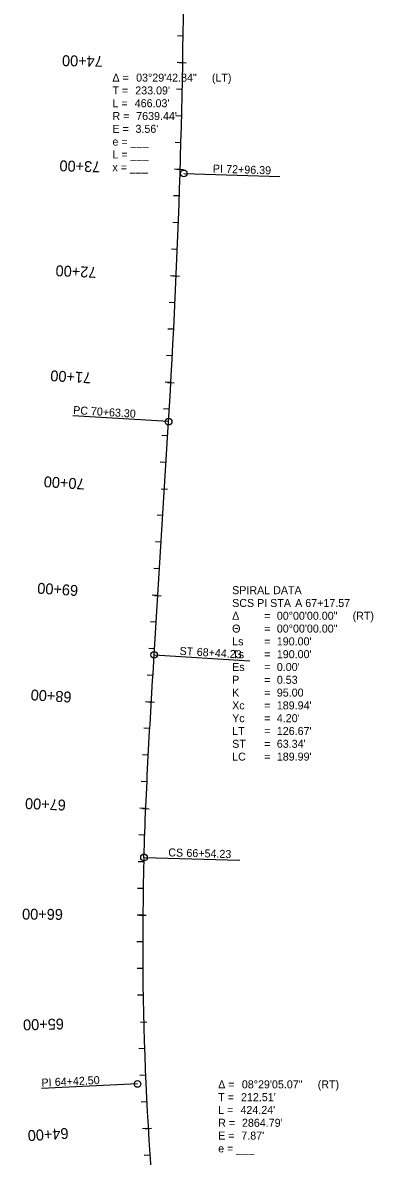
# Model space of a CAD drawing. Extents: x 11526485 to 11527255, y 9590594 to 9599170.
# Drawn here: x 11526485 to 11526814, y 9594882 to 9595945 of the extents above; entities that cross this region are included whole.
import ezdxf

# ---------------------------------------------------------------- set-up
doc = ezdxf.new("R2010")
doc.units = 0
for name, color, linetype in [('Alignment', 7, 'Continuous'), ('Default', 7, 'Continuous'), ('TextAlignment', 7, 'Continuous'), ('TextAlignmentLrg', 7, 'Continuous'), ('TextAlignmentSml', 7, 'Continuous')]:
    doc.layers.add(name, color=color, linetype=linetype)

msp = doc.modelspace()

# ---------------------------------------------------------------- linework, layer by layer
at = {"layer": 'Alignment'}
msp.add_line((11526608.5, 9595352.3), (11526622, 9595570.9), dxfattribs=at)
for centre, radius, start, end in [((11518997, 9596041.3), 7639.4, 356.46953, 359.96476), ((11529462.5, 9595081), 2864.8, 178.3695, 186.8543)]:
    msp.add_arc(centre, radius, start, end, dxfattribs=at)
msp.add_open_spline([(11526598.9, 9595162.5), (11526599.3, 9595178.3), (11526600.5, 9595210), (11526602.9, 9595257.4), (11526605.5, 9595304.8), (11526607.5, 9595336.4), (11526608.5, 9595352.3)], degree=3, dxfattribs=at)
at = {"layer": 'Default'}
msp.add_line((11526608.5, 9595352.3), (11526622, 9595570.9), dxfattribs=at)
for centre, radius, start, end in [((11518997, 9596041.3), 7639.4, 356.46953, 359.96476), ((11529462.5, 9595081), 2864.8, 178.3695, 186.8543)]:
    msp.add_arc(centre, radius, start, end, dxfattribs=at)
msp.add_open_spline([(11526598.9, 9595162.5), (11526599.3, 9595178.3), (11526600.5, 9595210), (11526602.9, 9595257.4), (11526605.5, 9595304.8), (11526607.5, 9595336.4), (11526608.5, 9595352.3)], degree=3, dxfattribs=at)
at = {"layer": 'TextAlignment'}
for p, q in [((11526636.3, 9595803.6), (11526726.3, 9595800.8)), ((11526726.3, 9595800.8), (11526726.3, 9595800.8)), ((11526622, 9595570.9), (11526532.2, 9595576.5)), ((11526532.2, 9595576.5), (11526532.2, 9595576.5)), ((11526608.5, 9595352.3), (11526698.3, 9595346.7)), ((11526698.3, 9595346.7), (11526698.3, 9595346.7)), ((11526598.9, 9595162.5), (11526688.9, 9595159.9)), ((11526598.9, 9595162.5), (11526688.9, 9595159.9)), ((11526688.9, 9595159.9), (11526688.9, 9595159.9)), ((11526688.9, 9595159.9), (11526688.9, 9595159.9)), ((11526592.8, 9594950.1), (11526502.9, 9594946)), ((11526502.9, 9594946), (11526502.9, 9594946))]:
    msp.add_line(p, q, dxfattribs=at)
for centre in [(11526636.3, 9595803.6), (11526622, 9595570.9), (11526608.5, 9595352.3), (11526598.9, 9595162.5), (11526598.9, 9595162.5), (11526592.8, 9594950.1)]:
    msp.add_circle(centre, 3.12, dxfattribs=at)
at = {"layer": 'TextAlignmentLrg'}
for p, q in [((11526635.3, 9595907.3), (11526629.9, 9595907.4)), ((11526632.9, 9595807.3), (11526627.4, 9595807.5)), ((11526629.2, 9595707.4), (11526623.7, 9595707.7)), ((11526624.2, 9595607.5), (11526618.7, 9595607.9)), ((11526615, 9595507.9), (11526621.1, 9595507.5)), ((11526611.9, 9595407.9), (11526606.5, 9595408.3)), ((11526605.8, 9595308.1), (11526600.4, 9595308.4)), ((11526600.5, 9595208.2), (11526595.1, 9595208.5)), ((11526597.9, 9595108.3), (11526592.4, 9595108.3)), ((11526595.6, 9595008.2), (11526601.7, 9595008.4)), ((11526602.9, 9594908.4), (11526597.5, 9594908.1))]:
    msp.add_line(p, q, dxfattribs=at)
at = {"layer": 'TextAlignmentSml'}
for p, q in [((11526635.7, 9595932.3), (11526630.2, 9595932.4)), ((11526632.3, 9595907.4), (11526638.4, 9595907.3)), ((11526634.8, 9595882.3), (11526629.4, 9595882.4)), ((11526634.3, 9595857.3), (11526628.8, 9595857.5)), ((11526633.6, 9595832.3), (11526628.2, 9595832.5)), ((11526629.8, 9595807.4), (11526636, 9595807.3)), ((11526632.1, 9595782.4), (11526626.6, 9595782.5)), ((11526631.2, 9595757.4), (11526625.8, 9595757.6)), ((11526630.2, 9595732.4), (11526624.8, 9595732.6)), ((11526626.1, 9595707.6), (11526632.2, 9595707.3)), ((11526628.1, 9595682.4), (11526622.6, 9595682.7)), ((11526626.8, 9595657.5), (11526621.4, 9595657.7)), ((11526625.5, 9595632.5), (11526620.1, 9595632.8)), ((11526621.1, 9595607.7), (11526627.2, 9595607.4)), ((11526622.7, 9595582.6), (11526617.3, 9595582.9)), ((11526621.2, 9595557.6), (11526615.7, 9595558)), ((11526619.6, 9595532.7), (11526614.2, 9595533)), ((11526615, 9595507.9), (11526621.1, 9595507.5)), ((11526616.6, 9595482.8), (11526611.1, 9595483.1)), ((11526615, 9595457.8), (11526609.6, 9595458.2)), ((11526613.5, 9595432.9), (11526608, 9595433.2)), ((11526608.9, 9595408.1), (11526615, 9595407.7)), ((11526610.4, 9595383), (11526604.9, 9595383.3)), ((11526608.9, 9595358), (11526603.4, 9595358.4)), ((11526607.3, 9595333.1), (11526601.9, 9595333.4)), ((11526602.7, 9595308.3), (11526608.9, 9595307.9)), ((11526604.3, 9595283.2), (11526598.9, 9595283.5)), ((11526603, 9595258.2), (11526597.5, 9595258.5)), ((11526601.7, 9595233.2), (11526596.2, 9595233.5)), ((11526597.5, 9595208.4), (11526603.6, 9595208.1)), ((11526599.6, 9595183.3), (11526594.1, 9595183.5)), ((11526598.8, 9595158.3), (11526593.3, 9595158.4)), ((11526598.2, 9595133.3), (11526592.8, 9595133.4)), ((11526594.8, 9595108.3), (11526600.9, 9595108.3)), ((11526597.7, 9595083.3), (11526592.3, 9595083.3)), ((11526597.8, 9595058.3), (11526592.4, 9595058.2)), ((11526598.1, 9595033.3), (11526592.7, 9595033.2)), ((11526595.6, 9595008.2), (11526601.7, 9595008.4)), ((11526599.4, 9594983.3), (11526593.9, 9594983.1)), ((11526600.4, 9594958.3), (11526594.9, 9594958.1)), ((11526601.5, 9594933.4), (11526596.1, 9594933.1)), ((11526599.9, 9594908.2), (11526606, 9594908.6)), ((11526604.6, 9594883.4), (11526599.1, 9594883.1))]:
    msp.add_line(p, q, dxfattribs=at)

# ---------------------------------------------------------------- texts
at = {"layer": 'TextAlignment'}
for s, p in [('Δ = ', (11526569.3, 9595889.6)), ('03°29\'42.84"', (11526591.5, 9595889.6)), (' (LT)', (11526659.8, 9595889.6)), ('T = ', (11526569.3, 9595877.6)), ("233.09'", (11526590.7, 9595877.6)), ('L = ', (11526569.3, 9595865.6)), ("466.03'", (11526590.2, 9595865.6)), ('R = ', (11526569.3, 9595853.6)), ("7639.44'", (11526591.6, 9595853.6)), ('E = ', (11526569.3, 9595841.6)), ("3.56'", (11526590.9, 9595841.6)), ('e = ___ ', (11526569.3, 9595829.6)), ('L = ___', (11526569.3, 9595817.6)), ('x = ___', (11526569.3, 9595805.6)), ('SPIRAL DATA', (11526681.6, 9595409.2)), ('SCS PI STA ', (11526681.6, 9595397.2)), ('A 67+17.57', (11526740.7, 9595397.2)), ('Δ', (11526681.6, 9595385.2)), ('= ', (11526711.6, 9595385.2)), ('00°00\'00.00"', (11526723.5, 9595385.2)), (' (RT)', (11526791.8, 9595385.2)), ('Θ ', (11526681.6, 9595373.2)), ('= ', (11526711.6, 9595373.2)), ('00°00\'00.00"', (11526723.5, 9595373.2)), ('Ls', (11526681.6, 9595361.2)), ('= ', (11526711.6, 9595361.2)), ("190.00'", (11526723.5, 9595361.2)), ('Ts', (11526681.6, 9595349.2)), ('= ', (11526711.6, 9595349.2)), ("190.00'", (11526723.5, 9595349.2)), ('Es', (11526681.6, 9595337.2)), ('= ', (11526711.6, 9595337.2)), ("0.00'", (11526723.5, 9595337.2)), ('P', (11526681.6, 9595325.2)), ('0.53', (11526723.5, 9595325.2)), ('= ', (11526711.6, 9595325.2)), ('K', (11526681.6, 9595313.2)), ('= ', (11526711.6, 9595313.2)), ('95.00', (11526723.5, 9595313.2)), ('Xc', (11526681.6, 9595301.2)), ('= ', (11526711.6, 9595301.2)), ("189.94'", (11526723.5, 9595301.2)), ('Yc', (11526681.6, 9595289.2)), ('= ', (11526711.6, 9595289.2)), ("4.20'", (11526723.5, 9595289.2)), ('LT', (11526681.6, 9595277.2)), ('= ', (11526711.6, 9595277.2)), ("126.67'", (11526723.5, 9595277.2)), ('ST ', (11526681.6, 9595265.2)), ('= ', (11526711.6, 9595265.2)), ("63.34'", (11526723.5, 9595265.2)), ('LC', (11526681.6, 9595253.2)), ('= ', (11526711.6, 9595253.2)), ("189.99'", (11526723.5, 9595253.2)), ('Δ = ', (11526668.5, 9594946)), ('08°29\'05.07"', (11526690.7, 9594946)), (' (RT)', (11526759.1, 9594946)), ('T = ', (11526668.5, 9594934)), ("212.51'", (11526689.9, 9594934)), ('L = ', (11526668.5, 9594922)), ("424.24'", (11526689.4, 9594922)), ('R = ', (11526668.5, 9594910)), ("2864.79'", (11526690.8, 9594910)), ('E = ', (11526668.5, 9594898)), ("7.87'", (11526690.2, 9594898)), ('e = ___ ', (11526668.5, 9594886))]:
    msp.add_text(s, height=7.5, dxfattribs=at).set_placement(p)
for s, rotation, p in [('PI ', 358.2171, (11526663.4, 9595804.4)), ('72+96.39', 358.2171, (11526675.9, 9595804)), ('PC', 356.4695, (11526532.3, 9595578.1)), ('70+63.30', 356.4695, (11526548.9, 9595577.1)), ('ST', 356.4695, (11526632.1, 9595352.4)), ('68+44.23', 356.4695, (11526648.2, 9595351.5)), ('CS', 358.3695, (11526621.6, 9595163.5)), ('CS', 358.3695, (11526621.6, 9595163.5)), ('66+54.23', 358.3695, (11526638.6, 9595163)), ('66+54.23', 358.3695, (11526638.6, 9595163)), ('PI ', 2.6119, (11526502.9, 9594947.6)), ('64+42.50', 2.6119, (11526515.4, 9594948.2))]:
    msp.add_text(s, height=7.5, rotation=rotation, dxfattribs=at).set_placement(p)
at = {"layer": 'TextAlignmentLrg'}
for s, rotation, p in [('70+00', 176.4695, (11526543.5, 9595517.4)), ('65+00', 181.4541, (11526523.6, 9595011.5))]:
    msp.add_text(s, height=10.2, rotation=rotation, dxfattribs=at).set_placement(p)
at = {"layer": 'TextAlignmentSml'}
for s, rotation, p in [('74+00', 178.9948, (11526560.4, 9595913.7)), ('73+00', 178.2448, (11526558.1, 9595814.7)), ('72+00', 177.4948, (11526554.5, 9595715.8)), ('71+00', 176.7448, (11526549.6, 9595616.9)), ('70+00', 176.4695, (11526543.5, 9595517.4)), ('69+00', 176.4695, (11526537.4, 9595417.6)), ('68+00', 176.5725, (11526531.2, 9595317.7)), ('67+00', 177.5643, (11526525.8, 9595216.5)), ('66+00', 179.4541, (11526522.9, 9595114.1)), ('65+00', 181.4541, (11526523.6, 9595011.5)), ('64+00', 183.4541, (11526527.8, 9594909))]:
    msp.add_text(s, height=10.2, rotation=rotation, dxfattribs=at).set_placement(p)

doc.saveas('drawing.dxf')
